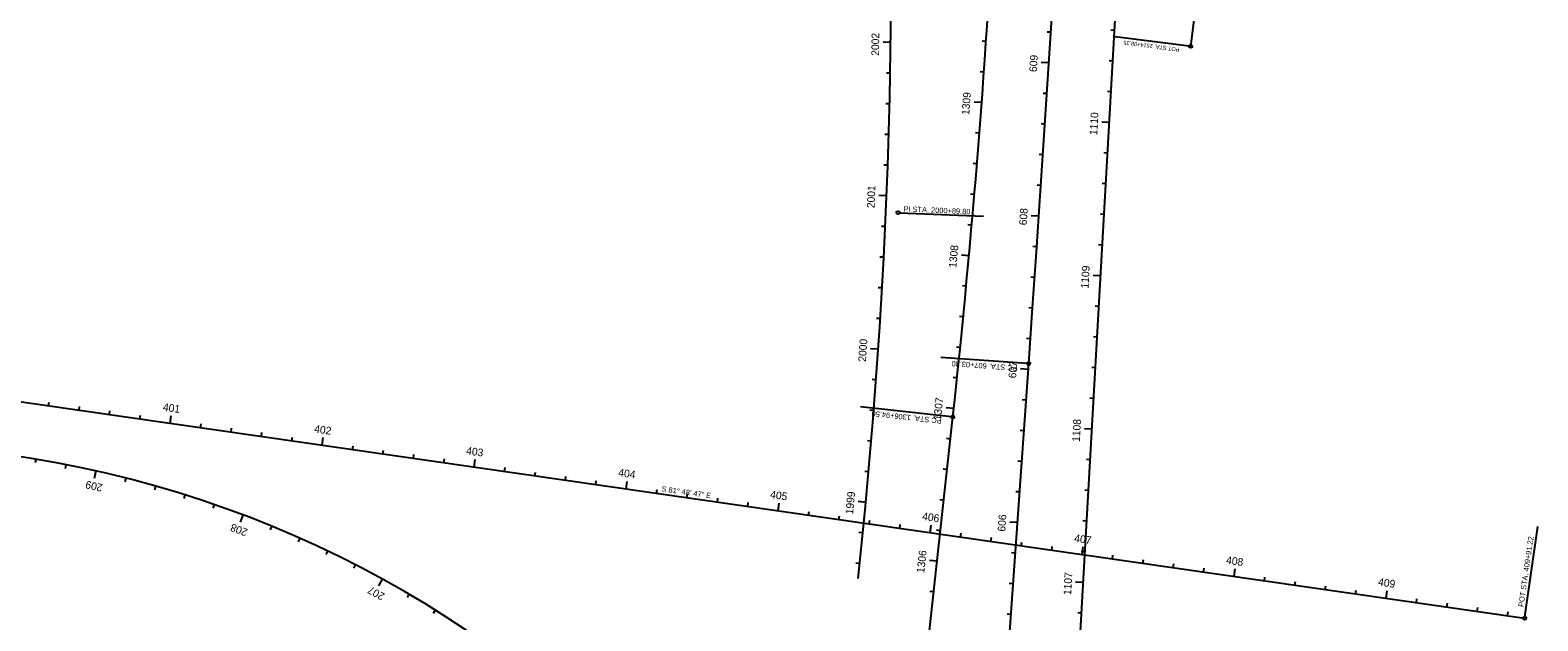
# Model space of a CAD drawing. Extents: x 919452 to 931278, y 583254 to 665650.
# Drawn here: x 928386 to 929368, y 636383 to 636768 of the extents above; entities that cross this region are included whole.
import ezdxf

# ---------------------------------------------------------------- set-up
doc = ezdxf.new("R2010")
doc.units = 0
for name, color, linetype in [('CLConst_dp', 7, 'Continuous'), ('CurveDataLabel_dp', 7, 'Continuous'), ('StationTicL_dp', 7, 'Continuous'), ('StationTicS_dp', 7, 'Continuous'), ('TextBLStation', 7, 'Continuous'), ('TextLabel', 7, 'Continuous')]:
    doc.layers.add(name, color=color, linetype=linetype)

msp = doc.modelspace()

# ---------------------------------------------------------------- linework, layer by layer
at = {"layer": 'CLConst_dp'}
for p, q in [((929063.91, 636273.75), (929152.38, 637830.35)), ((929141.47, 636757.31), (929241.91, 637546.46)), ((928999.45, 636034.27), (929035.97, 636550.78)), ((928273.35, 636541.15), (929358.98, 636384.96)), ((928945.89, 636143.25), (928986.58, 636516.04))]:
    msp.add_line(p, q, dxfattribs=at)
for centre, radius, start, end in [((900459.43, 638571.38), 28647.89, 355.955427, 0.622371), ((923022, 637167.05), 6000, 353.771004, 0.562502), ((926819.39, 639157.21), 2817.49, 300.15904, 311.0304), ((925288.17, 636807.76), 3658.23, 353.771, 1.26779), ((928270.99, 635782.23), 716.2, 0.06217, 82.06007)]:
    msp.add_arc(centre, radius, start, end, dxfattribs=at)
at = {"layer": 'CurveDataLabel_dp'}
for p, q in [((929140.48, 636757.43), (929092.21, 636763.58)), ((928951.8, 636649.04), (929006.64, 636646.67)), ((929034.97, 636550.85), (928978.85, 636554.82)), ((928985.59, 636516.15), (928926.53, 636522.59)), ((929359.12, 636385.95), (929367.59, 636444.79))]:
    msp.add_line(p, q, dxfattribs=at)
for centre in [(929141.47, 636757.31), (928950.8, 636649.09), (929035.97, 636550.78), (928986.58, 636516.04), (929358.98, 636384.96)]:
    msp.add_circle(centre, 1, dxfattribs=at)
at = {"layer": 'StationTicL_dp'}
for p, q in [((928946.08, 636759.92), (928941.08, 636759.99)), ((929049.14, 636746.53), (929044.15, 636746.85)), ((929005.37, 636720.67), (929000.39, 636721.04)), ((929088.57, 636707.74), (929083.58, 636708.03)), ((928943.41, 636659.96), (928938.41, 636660.16)), ((929042.59, 636646.75), (929037.6, 636647.08)), ((928997.1, 636621.02), (928992.12, 636621.47)), ((929082.9, 636607.91), (929077.91, 636608.19)), ((928938, 636560.11), (928933.02, 636560.45)), ((929035.7, 636546.98), (929030.71, 636547.34)), ((928987.17, 636521.51), (928982.2, 636522.05)), ((928476.85, 636511.88), (928477.56, 636516.83)), ((928575.83, 636497.64), (928576.54, 636502.59)), ((929077.22, 636508.07), (929072.23, 636508.35)), ((928428.47, 636480.9), (928427.37, 636476.02)), ((928674.81, 636483.4), (928675.52, 636488.35)), ((928773.79, 636469.16), (928774.5, 636474.11)), ((928524.17, 636452.19), (928522.4, 636447.51)), ((928872.77, 636454.92), (928873.48, 636459.86)), ((928929.87, 636460.44), (928924.89, 636460.92)), ((928971.75, 636440.68), (928972.46, 636445.62)), ((929028.65, 636447.23), (929023.66, 636447.59)), ((928976.33, 636422.1), (928971.36, 636422.64)), ((929070.73, 636426.43), (929071.44, 636431.38)), ((929169.71, 636412.19), (929170.43, 636417.14)), ((928614.95, 636410.43), (928612.55, 636406.04)), ((929071.55, 636408.23), (929066.56, 636408.51)), ((929268.69, 636397.95), (929269.41, 636402.9))]:
    msp.add_line(p, q, dxfattribs=at)
at = {"layer": 'StationTicS_dp'}
for p, q in [((929050.4, 636766.49), (929047.91, 636766.65)), ((929091.98, 636767.65), (929089.48, 636767.79)), ((929008.22, 636760.57), (929005.72, 636760.74)), ((929090.84, 636747.68), (929088.35, 636747.82)), ((928945.77, 636739.92), (928943.27, 636739.97)), ((929006.83, 636740.62), (929004.34, 636740.8)), ((929047.86, 636726.57), (929045.36, 636726.73)), ((929089.71, 636727.71), (929087.21, 636727.85)), ((928945.34, 636719.93), (928942.84, 636719.99)), ((929046.56, 636706.62), (929044.07, 636706.78)), ((928944.81, 636699.93), (928942.31, 636700.01)), ((929003.85, 636700.73), (929001.36, 636700.92)), ((929087.44, 636687.78), (929084.94, 636687.92)), ((928944.16, 636679.95), (928941.66, 636680.03)), ((929002.27, 636680.79), (928999.77, 636681)), ((929045.25, 636686.66), (929042.76, 636686.82)), ((929086.3, 636667.81), (929083.81, 636667.95)), ((929000.61, 636660.86), (928998.12, 636661.07)), ((929043.93, 636666.7), (929041.43, 636666.87)), ((929085.17, 636647.84), (929082.67, 636647.98)), ((928942.55, 636639.98), (928940.05, 636640.09)), ((928998.89, 636640.94), (928996.4, 636641.15)), ((928941.58, 636620), (928939.08, 636620.13)), ((929041.24, 636626.79), (929038.75, 636626.96)), ((929084.03, 636627.87), (929081.54, 636628.01)), ((928940.49, 636600.03), (928938, 636600.17)), ((928995.25, 636601.1), (928992.76, 636601.34)), ((929039.88, 636606.84), (929037.38, 636607.01)), ((928939.3, 636580.07), (928936.81, 636580.22)), ((928993.33, 636581.19), (928990.84, 636581.44)), ((929038.5, 636586.89), (929036, 636587.06)), ((929081.76, 636587.94), (929079.27, 636588.08)), ((928991.34, 636561.29), (928988.86, 636561.55)), ((929037.11, 636566.94), (929034.61, 636567.11)), ((929080.63, 636567.97), (929078.13, 636568.11)), ((928936.6, 636540.16), (928934.1, 636540.34)), ((928989.29, 636541.4), (928986.81, 636541.66)), ((929079.49, 636548), (929077, 636548.14)), ((928397.66, 636523.27), (928398.02, 636525.74)), ((928417.46, 636520.42), (928417.81, 636522.9)), ((928935.08, 636520.22), (928932.59, 636520.41)), ((929034.29, 636527.03), (929031.8, 636527.21)), ((929078.36, 636528.03), (929075.86, 636528.18)), ((928437.25, 636517.57), (928437.61, 636520.05)), ((928457.05, 636514.73), (928457.41, 636517.2)), ((928496.64, 636509.03), (928497, 636511.5)), ((928516.44, 636506.18), (928516.8, 636508.66)), ((928536.24, 636503.33), (928536.59, 636505.81)), ((928556.03, 636500.49), (928556.39, 636502.96)), ((928933.45, 636500.28), (928930.96, 636500.49)), ((928985.01, 636501.63), (928982.52, 636501.9)), ((929032.88, 636507.08), (929030.38, 636507.26)), ((928595.62, 636494.79), (928595.98, 636497.26)), ((928615.42, 636491.94), (928615.78, 636494.42)), ((928635.22, 636489.09), (928635.57, 636491.57)), ((928389.22, 636488.6), (928388.81, 636486.14)), ((928408.9, 636485.03), (928408.42, 636482.57)), ((928655.01, 636486.24), (928655.37, 636488.72)), ((928694.61, 636480.55), (928694.96, 636483.02)), ((928982.84, 636481.75), (928980.35, 636482.02)), ((929031.47, 636487.13), (929028.97, 636487.31)), ((929076.09, 636488.1), (929073.59, 636488.24)), ((928447.91, 636476.23), (928447.3, 636473.81)), ((928467.22, 636471.02), (928466.54, 636468.62)), ((928714.4, 636477.7), (928714.76, 636480.17)), ((928734.2, 636474.85), (928734.55, 636477.33)), ((928753.99, 636472), (928754.35, 636474.48)), ((928931.72, 636480.36), (928929.23, 636480.58)), ((928486.38, 636465.27), (928485.63, 636462.89)), ((928793.59, 636466.31), (928793.94, 636468.78)), ((928813.38, 636463.46), (928813.74, 636465.93)), ((928833.18, 636460.61), (928833.53, 636463.09)), ((928980.67, 636461.86), (928978.18, 636462.14)), ((929030.06, 636467.18), (929027.56, 636467.36)), ((929074.95, 636468.13), (929072.46, 636468.27)), ((928505.37, 636458.99), (928504.55, 636456.63)), ((928852.97, 636457.76), (928853.33, 636460.24)), ((928892.57, 636452.07), (928892.92, 636454.54)), ((928912.36, 636449.22), (928912.72, 636451.69)), ((928542.78, 636444.86), (928541.83, 636442.54)), ((928932.16, 636446.37), (928932.52, 636448.85)), ((928951.96, 636443.52), (928952.31, 636446)), ((928978.5, 636441.98), (928976.01, 636442.25)), ((929073.82, 636448.16), (929071.32, 636448.3)), ((928561.17, 636437.01), (928560.16, 636434.72)), ((928927.92, 636440.54), (928925.43, 636440.79)), ((928991.55, 636437.83), (928991.9, 636440.3)), ((929011.34, 636434.98), (929011.7, 636437.45)), ((929031.14, 636432.13), (929031.5, 636434.61)), ((929050.94, 636429.28), (929051.29, 636431.76)), ((928579.34, 636428.65), (928578.27, 636426.39)), ((929027.24, 636427.28), (929024.74, 636427.46)), ((929072.68, 636428.2), (929070.19, 636428.34)), ((929090.53, 636423.59), (929090.88, 636426.06)), ((929110.32, 636420.74), (929110.68, 636423.21)), ((928597.27, 636419.79), (928596.13, 636417.56)), ((928925.86, 636420.65), (928923.37, 636420.91)), ((929130.12, 636417.89), (929130.48, 636420.36)), ((929149.92, 636415.04), (929150.27, 636417.52)), ((928974.16, 636402.22), (928971.67, 636402.49)), ((929025.83, 636407.33), (929023.33, 636407.51)), ((929189.51, 636409.35), (929189.87, 636411.82)), ((929209.31, 636406.5), (929209.66, 636408.97)), ((929229.1, 636403.65), (929229.46, 636406.12)), ((929248.9, 636400.8), (929249.25, 636403.28)), ((928632.35, 636400.58), (928631.09, 636398.42)), ((929288.49, 636395.11), (929288.85, 636397.58)), ((929308.29, 636392.26), (929308.64, 636394.73)), ((928649.48, 636390.25), (928648.16, 636388.13)), ((929024.41, 636387.38), (929021.92, 636387.56)), ((929070.42, 636388.26), (929067.92, 636388.4)), ((929328.08, 636389.41), (929328.44, 636391.88)), ((929347.88, 636386.56), (929348.23, 636389.04))]:
    msp.add_line(p, q, dxfattribs=at)

# ---------------------------------------------------------------- texts
at = {"layer": 'CurveDataLabel_dp'}
for s, height, rotation, p in [('POT STA. 2514+08.35', 2.625, 172.74679, (929134.31, 636756.46)), ('PI STA. 2000+89.80', 3.5, 357.5194, (928954.34, 636649.81)), ('PC STA. 607+03.80', 3.5, 175.95543, (929028.86, 636549.53)), ('PC STA. 1306+94.50', 3.5, 173.771, (928979.43, 636515.06)), ('POT STA. 409+91.22', 3.5, 81.81299, (929358.25, 636392.14))]:
    msp.add_text(s, height=height, rotation=rotation, dxfattribs=at).set_placement(p)
at = {"layer": 'TextBLStation'}
for s, rotation, p in [('2002', 89.25072, (928938.47, 636751.19)), ('609', 86.34782, (929041.24, 636740.49)), ('1309', 85.73342, (928997.24, 636712.48)), ('1110', 86.74679, (929080.59, 636699.42)), ('2001', 87.68451, (928935.58, 636651.89)), ('608', 86.14782, (929034.67, 636640.69)), ('1308', 84.77849, (928988.83, 636612.92)), ('1109', 86.74679, (929074.91, 636599.57)), ('2000', 86.11829, (928929.93, 636551.87)), ('607', 85.95543, (929027.76, 636541.06)), ('401', 351.81299, (928471.84, 636520.17)), ('1307', 83.82356, (928978.78, 636513.65)), ('402', 351.81299, (928570.38, 636506)), ('1108', 86.74679, (929069.24, 636499.69)), ('403', 351.81299, (928669.35, 636491.76)), ('404', 351.81299, (928768.44, 636477.5)), ('209', 167.29833, (928433.19, 636472.15)), ('405', 351.81299, (928867.34, 636463.27)), ('1999', 84.55208, (928921.57, 636452.42)), ('406', 351.81299, (928966.35, 636449.03)), ('606', 85.95543, (929020.7, 636441.25)), ('208', 159.29837, (928527.67, 636442.85)), ('407', 351.81299, (929065.39, 636434.78)), ('1306', 83.771, (928967.92, 636414.19)), ('408', 351.81299, (929164.28, 636420.55)), ('1107', 86.74679, (929063.57, 636399.95)), ('207', 151.2984, (928617.02, 636400.74)), ('409', 351.81299, (929263.3, 636406.31))]:
    msp.add_text(s, height=5, rotation=rotation, dxfattribs=at).set_placement(p)
at = {"layer": 'TextLabel'}
msp.add_text('S 81%%d 48\' 47" E', height=3.5, rotation=351.81299, dxfattribs=at).set_placement((928796.69, 636467.63))

doc.saveas('drawing.dxf')
